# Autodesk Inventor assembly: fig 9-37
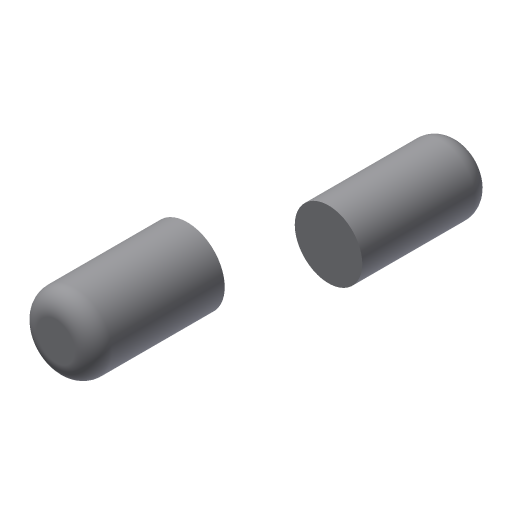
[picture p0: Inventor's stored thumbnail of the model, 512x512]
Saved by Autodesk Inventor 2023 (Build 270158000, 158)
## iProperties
Created: 2013-07
Part Number: fig 9-37
Document SubType Name: Assembly
Designer: CADCIM
Author: CADCIM
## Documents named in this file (3)
- D:\PROJECTS\Project 2022\Autodesk Inventor For Professional 2023\RESOURCES INVENTOR 2023\RESOURCES INVENTOR 2023\Inventor_2023_Part\Inventor_2023_Part\c09_Inv_2023_prt\fig 9-38.iam
- D:\PROJECTS\Project 2022\Autodesk Inventor For Professional 2023\RESOURCES INVENTOR 2023\RESOURCES INVENTOR 2023\Inventor_2023_Part\Inventor_2023_Part\c09_Inv_2023_prt\10.ipt
- D:\PROJECTS\Project 2022\Autodesk Inventor For Professional 2023\RESOURCES INVENTOR 2023\RESOURCES INVENTOR 2023\Inventor_2023_Part\Inventor_2023_Part\c09_Inv_2023_prt\11.ipt
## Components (2 placed, 2 different names)
1. 10:1
2. 11:1
